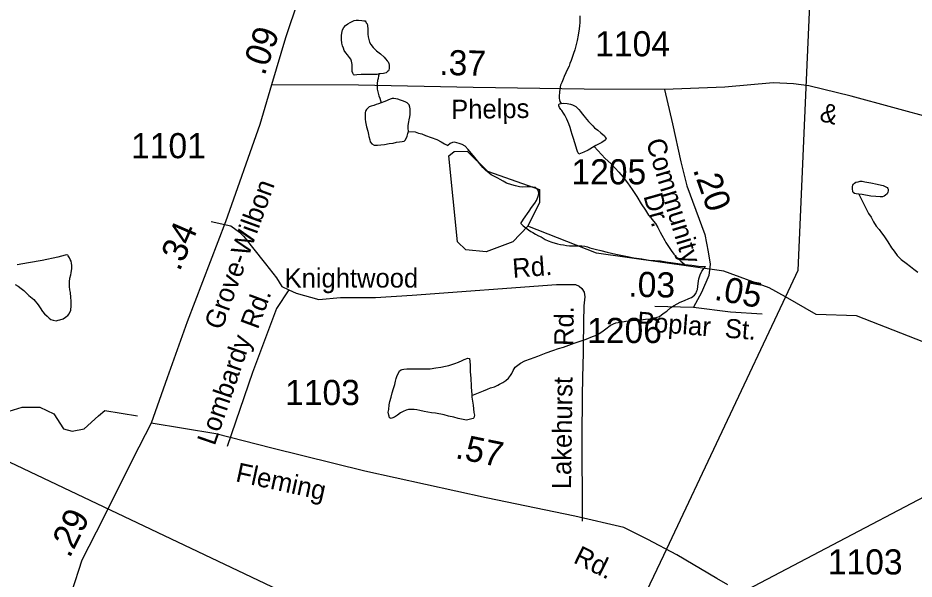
# Model space of a CAD drawing. Extents: x 2001466 to 2224147, y 644118 to 847247.
# Drawn here: x 2046028 to 2050483, y 665173 to 667963 of the extents above; entities that cross this region are included whole.
import ezdxf

# ---------------------------------------------------------------- set-up
doc = ezdxf.new("R2010")
doc.units = 0
for name, color, linetype in [('Exist Hydrographic Creek Single Shore', 7, 'Continuous'), ('Exist Hydrographic Misc Water Feature', 7, 'Continuous'), ('Exist Railroad Mainline', 7, 'Continuous'), ('Exist Road Non-System Type 51', 7, 'Continuous'), ('Exist Road Non-System Type 51 Label', 7, 'Continuous'), ('Exist Road Secondary Mileage Hundredths English Label', 7, 'Continuous'), ('Exist Road Secondary Type 41 Attributed', 7, 'Continuous'), ('Exist Road Secondary Type 51 Attributed', 7, 'Continuous'), ('Exist Road Secondary Type 51 Label', 7, 'Continuous'), ('Exist Road Secondary Type 51 Number Label', 7, 'Continuous'), ('Exist Utilities Electrical Transmission Line', 7, 'Continuous')]:
    doc.layers.add(name, color=color, linetype=linetype)

msp = doc.modelspace()

# ---------------------------------------------------------------- linework, layer by layer
at = {"layer": 'Exist Hydrographic Creek Single Shore'}
for points in [[(2049843.6, 666575.6), (2049763.4, 666621.1), (2049538.4, 666704.4), (2048905.4, 666792.7), (2048563.4, 666927.6)], [(2053273.2, 665427.7), (2053006.3, 665420.1), (2052782.4, 665359), (2052490.4, 665574.9), (2052414.3, 665701.1), (2052256.4, 665832.3), (2052022.2, 665948.5), (2051756.3, 665950.7), (2051539.3, 665974.8), (2051155.3, 666107.3), (2050197.3, 666481), (2049997.3, 666488.4), (2049843.6, 666575.6)]]:
    msp.add_lwpolyline(points, dxfattribs=at)
at = {"layer": 'Exist Hydrographic Misc Water Feature'}
for points in [[(2048822, 667974), (2048822, 667950), (2048822, 667940), (2048819.9, 667923.9), (2048818.1, 667907.9), (2048814, 667878), (2048808, 667850), (2048802.1, 667824), (2048796.1, 667804), (2048790.2, 667785.9), (2048786.3, 667775.9), (2048778.3, 667752), (2048772.4, 667736), (2048768.5, 667723.9), (2048760.5, 667707.9), (2048752.5, 667689.9), (2048744.5, 667671.9), (2048738.5, 667657.9), (2048732.6, 667641.9), (2048726.4, 667627.9), (2048722.5, 667609.9), (2048720.7, 667591.9), (2048718.6, 667575.8), (2048718.6, 667561.8), (2048720.7, 667555.9), (2048722.5, 667547.9), (2048728.7, 667537.9)], [(2047824.6, 667684.2), (2047812.7, 667682.1), (2047798.6, 667682.1), (2047782.6, 667682.1), (2047764.7, 667682.1), (2047734.6, 667682), (2047712.6, 667679.9), (2047700.5, 667677.9), (2047696.7, 667681.9), (2047692.5, 667687.9), (2047690.7, 667695.9), (2047690.5, 667705.9), (2047690.5, 667721.9), (2047690.5, 667732), (2047686.6, 667747.9), (2047682.5, 667757.9), (2047676.6, 667765.9), (2047666.3, 667779.9), (2047658.3, 667789.8), (2047650.3, 667801.8), (2047646.4, 667811.8), (2047642.3, 667823.8), (2047638.4, 667837.8), (2047636.4, 667855.8), (2047636.4, 667865.8), (2047636.4, 667875.8), (2047638.2, 667887.8), (2047642.3, 667903.8), (2047648.1, 667915.8), (2047656.1, 667925.8), (2047668.1, 667933.8), (2047680.2, 667939.9), (2047690.1, 667945.9), (2047700.1, 667949.9), (2047710.2, 667951.9), (2047722.1, 667951.9), (2047738.1, 667949.9), (2047748.1, 667948), (2047754.1, 667948), (2047758.2, 667944), (2047760.2, 667938), (2047764.1, 667934), (2047766.2, 667926), (2047766.2, 667920), (2047768.2, 667912), (2047768.2, 667906), (2047768.2, 667900), (2047768.2, 667890), (2047768.2, 667882), (2047770.3, 667868.1), (2047772.3, 667856.1), (2047776.2, 667842.1), (2047782.4, 667830.1), (2047794.5, 667816.1), (2047810.5, 667800.1), (2047830.3, 667784.2), (2047848.4, 667768.2), (2047856.4, 667760.2), (2047864.4, 667750.3), (2047868.5, 667744.3), (2047872.6, 667736.3), (2047874.4, 667728.3), (2047874.4, 667718.3), (2047874.4, 667712.3), (2047872.6, 667704.3), (2047870.5, 667700.2), (2047866.4, 667696.2), (2047858.4, 667690.2), (2047852.5, 667688.2), (2047846.5, 667686.2), (2047828.7, 667684.2), (2047824.6, 667684.2)], [(2047824.6, 667684.2), (2047820.7, 667674.2), (2047818.7, 667662.2), (2047816.6, 667652.2), (2047814.6, 667636.2), (2047814.6, 667626.2), (2047814.8, 667608.2), (2047818.7, 667588.2), (2047822.8, 667576.2), (2047826.9, 667564.2), (2047834.9, 667540.2)], [(2047834.9, 667540.2), (2047820.9, 667536.2), (2047808.8, 667532.2), (2047796.9, 667528.1), (2047784.8, 667524.1), (2047775, 667520.1), (2047766.8, 667512), (2047760.8, 667508), (2047756.9, 667500), (2047754.9, 667492.1), (2047755.1, 667482.1), (2047755.1, 667474.1), (2047755.1, 667460.1), (2047756.9, 667446.1), (2047761, 667422.1), (2047767.2, 667400.1), (2047771.1, 667384.1), (2047773.1, 667374.1), (2047777, 667356.2), (2047779.3, 667346.1), (2047787.3, 667336.2), (2047799.2, 667330.2), (2047815.2, 667330.2), (2047833.2, 667332.3), (2047851.3, 667334.3), (2047873.2, 667338.3), (2047893.3, 667340.4), (2047911.1, 667344.4), (2047925.1, 667346.5), (2047939, 667348.5), (2047949.1, 667350.5), (2047955.2, 667356.5), (2047963.2, 667374.5), (2047967.1, 667388.5), (2047969.2, 667398.5)], [(2047969.2, 667398.5), (2047969, 667414.5), (2047969, 667428.5), (2047971, 667446.5), (2047973.1, 667456.5), (2047977, 667470.5), (2047978.8, 667482.5), (2047978.8, 667496.5), (2047978.8, 667510.5), (2047977, 667518.5), (2047972.9, 667530.5), (2047962.8, 667540.4), (2047952.8, 667546.4), (2047940.7, 667550.4), (2047930.8, 667554.4), (2047916.7, 667558.4), (2047906.8, 667560.3), (2047896.8, 667562.3), (2047888.8, 667562.3), (2047878.7, 667558.3), (2047852.7, 667548.2), (2047834.9, 667540.2)], [(2048892.9, 667324.2), (2048863.2, 667306.2), (2048841, 667296.2), (2048825.1, 667288.1), (2048817.1, 667286.1), (2048815.2, 667290.1), (2048811.1, 667294.1), (2048807.2, 667308.1), (2048802.9, 667320.1), (2048797, 667342), (2048791, 667364), (2048783, 667384), (2048778.9, 667400), (2048773, 667418), (2048766.8, 667436), (2048762.9, 667448), (2048756.8, 667460), (2048746.7, 667480), (2048740.8, 667489.9), (2048732.8, 667501.9), (2048726.8, 667507.9), (2048720.7, 667517.9), (2048716.8, 667525.9), (2048716.6, 667531.8), (2048720.7, 667535.9), (2048728.7, 667537.9)], [(2048728.7, 667537.9), (2048738.7, 667539.9), (2048758.6, 667538), (2048774.6, 667534), (2048784.7, 667530), (2048794.7, 667526), (2048802.7, 667522), (2048808.6, 667516), (2048816.6, 667508.1), (2048824.8, 667498.1), (2048832.8, 667486.1), (2048842.7, 667474.1), (2048848.8, 667468.2), (2048856.8, 667458.2), (2048864.8, 667448.2), (2048886.8, 667426.2), (2048894.8, 667416.2), (2048911, 667404.3), (2048927, 667392.3), (2048944.8, 667376.4), (2048947.1, 667370.4), (2048953, 667362.4), (2048951, 667358.4), (2048947.1, 667354.4), (2048931.1, 667344.3), (2048900.9, 667328.3), (2048892.9, 667324.2)], [(2047969.2, 667398.5), (2048003.2, 667396.5), (2048019.2, 667390.6), (2048037, 667386.7), (2048055.1, 667378.7), (2048083.2, 667368.7), (2048111.1, 667358.8), (2048133.2, 667346.8), (2048149.2, 667336.8), (2048165.2, 667328.9)], [(2048527.7, 666941.6), (2048541.7, 666961.6), (2048569.8, 667001.7), (2048581.7, 667019.7), (2048597.6, 667041.7), (2048605.6, 667055.8), (2048613.4, 667071.8), (2048617.5, 667087.8), (2048615.5, 667103.8), (2048611.4, 667109.8), (2048599.5, 667119.7), (2048587.4, 667121.7), (2048575.5, 667123.7), (2048559.5, 667123.6), (2048537.6, 667121.6), (2048521.6, 667123.6), (2048501.5, 667127.5), (2048483.4, 667133.5), (2048457.4, 667141.5), (2048441.4, 667151.4), (2048425.4, 667159.4), (2048413.3, 667165.4), (2048381.3, 667183.3), (2048353.4, 667205.3), (2048339.3, 667219.2), (2048325.3, 667237.2), (2048313.2, 667253.2), (2048293.1, 667277.2), (2048281.3, 667291.1), (2048267.1, 667309.1), (2048251.1, 667325), (2048237.2, 667333), (2048221.2, 667338.9), (2048199, 667344.9), (2048189.2, 667342.9), (2048177.1, 667338.9), (2048165.2, 667328.9)], [(2048892.9, 667324.2), (2048947.1, 667264.3), (2048975.2, 667238.4), (2048997.3, 667216.5), (2049015.1, 667196.5), (2049037.3, 667170.5), (2049059.4, 667142.6), (2049081.4, 667110.6), (2049105.6, 667074.7), (2049127.5, 667038.7), (2049147.6, 667006.8), (2049163.6, 666982.8), (2049173.6, 666972.9), (2049179.6, 666962.9), (2049197.6, 666940.9), (2049209.7, 666920.9), (2049221.6, 666896.9), (2049229.8, 666883), (2049243.8, 666857), (2049249.9, 666847), (2049275.8, 666807), (2049289.9, 666789.1), (2049304.1, 666771.1), (2049323.9, 666753.1), (2049344, 666737.2)], [(2048563.4, 666927.6), (2048488.4, 666850.4), (2048355.3, 666800.7), (2048255.4, 666809.2), (2048213.4, 666849.5), (2048171.3, 667276.9), (2048196.4, 667299.3), (2048262.4, 667301.2), (2048362.5, 667200.8), (2048621.4, 667110.2), (2048621.4, 667044.6), (2048563.4, 666927.6)], [(2050209.2, 667086.8), (2050195.2, 667088.7), (2050187.2, 667090.7), (2050181.3, 667094.7), (2050179.2, 667098.7), (2050177.2, 667114.7), (2050177.2, 667124.7), (2050179, 667130.7), (2050183.1, 667136.7), (2050187, 667140.7), (2050193.2, 667146.7), (2050205.1, 667148.7), (2050215.1, 667150.7), (2050225.1, 667150.7), (2050239.1, 667148.8), (2050269, 667142.8), (2050299.2, 667136.9), (2050321.1, 667131), (2050329.1, 667129), (2050339.2, 667125), (2050343.1, 667123), (2050349, 667119), (2050353.1, 667115), (2050355.2, 667111), (2050355.2, 667103), (2050353.1, 667097), (2050349.2, 667089), (2050341.2, 667081), (2050335.3, 667077), (2050327.3, 667072.9), (2050315.2, 667072.9), (2050293.2, 667074.9), (2050269.2, 667076.9), (2050225.1, 667084.8), (2050209.2, 667086.8)], [(2050209.2, 667086.8), (2050247.3, 667010.8), (2050257.3, 666990.9), (2050269.4, 666972.9), (2050281.5, 666948.9), (2050295.5, 666926.9), (2050309.4, 666910.9), (2050321.5, 666895), (2050333.6, 666879), (2050353.5, 666849.1), (2050371.8, 666819.1), (2050383.7, 666803.1), (2050399.6, 666781.1), (2050419.7, 666761.2), (2050443.7, 666743.3), (2050465.9, 666727.3), (2050481.9, 666713.3), (2050501.8, 666699.4)], [(2048527.7, 666941.6), (2048539.8, 666929.6), (2048553.8, 666919.6), (2048565.9, 666909.7), (2048577.8, 666901.7), (2048587.8, 666895.8), (2048602, 666887.8), (2048615.9, 666879.8), (2048629.8, 666873.8), (2048649.9, 666861.8), (2048663.9, 666853.9), (2048681.9, 666847.9), (2048710, 666840), (2048726, 666836), (2048740, 666834), (2048756, 666832.1), (2048769.9, 666830.1), (2048785.9, 666830.1), (2048800, 666830.1), (2048819.9, 666830.2), (2048832, 666830.2), (2048846, 666828.2), (2048859.9, 666824.3), (2048872, 666820.3), (2048898.1, 666812.4), (2048925.9, 666806.4), (2048957.9, 666798.5), (2049000, 666788.5), (2049050, 666778.7), (2049090, 666770.7), (2049130, 666764.8), (2049166.1, 666758.8), (2049222, 666755), (2049249.9, 666751), (2049273.9, 666747), (2049344, 666737.2)], [(2046014.8, 666637), (2046029, 666629), (2046045, 666617), (2046056.8, 666607.1), (2046070.8, 666595.1), (2046082.9, 666583.1), (2046107.1, 666563.2), (2046129, 666537.2), (2046139.1, 666521.2), (2046151, 666503.3), (2046161, 666491.3), (2046173.1, 666479.3), (2046183.2, 666469.4), (2046191.2, 666463.4), (2046203.1, 666459.4), (2046219, 666457.4), (2046229.1, 666459.4), (2046237.1, 666461.4), (2046253.1, 666467.5), (2046265.2, 666475.5), (2046271.1, 666479.5), (2046277.1, 666483.5), (2046283, 666491.6), (2046291, 666509.5), (2046293.1, 666531.5), (2046292.9, 666555.5), (2046290.8, 666573.5), (2046289, 666597.5), (2046286.9, 666611.5), (2046284.7, 666627.5), (2046284.7, 666643.5), (2046284.7, 666651.5), (2046286.7, 666669.5), (2046290.6, 666685.5), (2046292.7, 666695.5), (2046296.6, 666717.5), (2046296.6, 666731.5), (2046294.7, 666743.5), (2046292.5, 666753.5), (2046288.6, 666761.5), (2046284.5, 666769.4), (2046278.5, 666779.4), (2046276.5, 666783.5), (2046270.5, 666785.4), (2046262.5, 666783.4), (2046226.4, 666773.3), (2046148.7, 666757.2), (2046080.6, 666745.1), (2046024.7, 666734.9)], [(2048285.4, 666085.3), (2048317.3, 666099.4), (2048343.4, 666109.4), (2048363.3, 666117.4), (2048377.4, 666123.5), (2048397.3, 666129.5), (2048413.3, 666137.6), (2048423.2, 666141.6), (2048439.1, 666149.6), (2048453.3, 666159.6), (2048467.2, 666171.7), (2048477.3, 666185.7), (2048483.2, 666195.7), (2048491, 666209.7), (2048501.1, 666225.7), (2048513.2, 666235.7), (2048527.1, 666245.8), (2048549.1, 666257.8), (2048576.9, 666267.8), (2048613, 666281.9), (2048655.1, 666298), (2048687.1, 666310), (2048714.9, 666320.1), (2048740.8, 666326.2), (2048792.9, 666346.2), (2048812.7, 666352.3), (2048832.8, 666358.3), (2048852.9, 666366.4), (2048884.7, 666378.4), (2048904.6, 666386.4), (2048930.7, 666402.5), (2048950.7, 666416.6), (2048972.7, 666434.5), (2048988.7, 666442.6), (2049000.6, 666446.6), (2049024.6, 666450.6), (2049050.6, 666454.7), (2049082.6, 666458.7), (2049112.5, 666460.8), (2049148.6, 666464.8), (2049174.7, 666466.9), (2049190.5, 666471), (2049206.4, 666475), (2049218.5, 666479), (2049236.4, 666493), (2049254.4, 666505), (2049274.5, 666523.1), (2049290.3, 666533.1), (2049306.3, 666541.2), (2049320.3, 666549.2), (2049342.4, 666557.2), (2049364.3, 666567.2), (2049376.4, 666573.3), (2049392.2, 666585.3), (2049398.2, 666593.3), (2049404.1, 666605.4), (2049406.2, 666613.4), (2049408.2, 666627.3), (2049410.3, 666643.3), (2049414.2, 666665.3), (2049420.1, 666685.4), (2049428.1, 666703.4), (2049440, 666719.4), (2049446, 666727.4)], [(2049344, 666737.2), (2049377.9, 666733.2), (2049411.9, 666729.3), (2049446, 666727.4)], [(2048285.4, 666085.3), (2048285.6, 666077.3), (2048291.5, 666037.3), (2048295.6, 666001.4), (2048297.7, 665987.4), (2048295.6, 665975.4), (2048291.5, 665971.3), (2048277.6, 665967.3), (2048257.7, 665963.3), (2048233.7, 665967.3), (2048217.5, 665971.2), (2048195.5, 665977.2), (2048169.5, 665983.1), (2048147.6, 665989.1), (2048103.7, 665997), (2048083.6, 665999), (2048047.5, 666006.9), (2048025.6, 666010.9), (2048011.6, 666014.8), (2047997.7, 666016.8), (2047983.5, 666016.8), (2047969.6, 666016.8), (2047957.7, 666012.7), (2047943.5, 666006.7), (2047929.6, 665998.7), (2047915.6, 665988.6), (2047899.7, 665978.6), (2047887.8, 665972.6), (2047883.7, 665970.6), (2047879.8, 665972.6), (2047875.7, 665974.6), (2047873.6, 665982.6), (2047871.8, 665988.6), (2047869.5, 666002.6), (2047871.6, 666016.5), (2047873.6, 666038.6), (2047877.5, 666056.6), (2047883.5, 666076.6), (2047889.4, 666098.6), (2047895.6, 666120.6), (2047901.3, 666140.6), (2047905.4, 666156.7), (2047909.3, 666170.6), (2047913.4, 666184.6), (2047921.2, 666200.6), (2047925.3, 666208.6), (2047933.3, 666212.6), (2047939.2, 666214.6), (2047947.2, 666216.7), (2047961.2, 666218.7), (2047979.2, 666218.8), (2047995.2, 666218.8), (2048009.2, 666218.8), (2048029.2, 666218.8), (2048047.3, 666218.9), (2048077.2, 666218.9), (2048105.1, 666222.9), (2048131.2, 666227), (2048153.3, 666231.1), (2048171.1, 666235.1), (2048201.1, 666245.1), (2048219.1, 666251.2), (2048237.2, 666259.2), (2048247, 666265.2), (2048265.1, 666271.3), (2048273.1, 666269.3), (2048277.2, 666237.3), (2048277.2, 666203.2), (2048279.2, 666171.3), (2048281.3, 666131.3), (2048283.3, 666103.3), (2048285.4, 666095.3), (2048285.4, 666085.3)]]:
    msp.add_lwpolyline(points, dxfattribs=at)
at = {"layer": 'Exist Railroad Mainline'}
msp.add_lwpolyline([(2046464.5, 663426.2), (2046524.6, 663459.1), (2048551.7, 664535.4), (2049194.6, 664876.7), (2049524.4, 665051.8), (2049557.2, 665070.3), (2052622.8, 666680.7), (2055671.2, 668278.9), (2056997.6, 668963.3), (2058840.6, 669936.5)], dxfattribs=at)
at = {"layer": 'Exist Road Non-System Type 51'}
for points in [[(2046989.7, 666951.2), (2047087, 666929.6), (2047130.2, 666897.2), (2047151.8, 666875.6), (2047195, 666821.6), (2047259.8, 666740.5), (2047313.8, 666670.3), (2047340.8, 666627.1), (2047375.2, 666611.2)], [(2047375.2, 666611.2), (2047411, 666594.6), (2047524.4, 666562.2), (2047632.4, 666573), (2047805.2, 666573), (2047988.8, 666583.8), (2048705.9, 666637.6), (2048769.9, 666638.3), (2048799.9, 666637.7), (2048817.7, 666629.3), (2048831.4, 666617.1), (2048843.1, 666598.8), (2048846.6, 666576.8), (2048841.7, 666530.9), (2048840.1, 666450.9), (2048837.1, 666206.9), (2048835, 666203), (2048831, 665907.1), (2048833.9, 665461)], [(2047375.2, 666611.2), (2047313.8, 666519), (2047195, 666200.3), (2047067.9, 665832)], [(2045729.8, 665879.7), (2045855.7, 665951.8), (2045942.1, 665995), (2046050.1, 666027.4), (2046136.5, 666027.4), (2046206.7, 665995), (2046255.3, 665919.3), (2046298.5, 665908.5), (2046357.9, 665919.3), (2046428.1, 665984.2), (2046460.5, 666011.2), (2046622.5, 665984.2)]]:
    msp.add_lwpolyline(points, dxfattribs=at)
at = {"layer": 'Exist Road Secondary Type 41 Attributed'}
msp.add_lwpolyline([(2049558.3, 665143.9), (2049503, 665175.3), (2049304.6, 665293.6), (2049160, 665369.6), (2049039.7, 665428.8), (2048796.9, 665485.8), (2048355.6, 665576.7), (2047752.9, 665709.7), (2047290.6, 665823.8), (2047011.9, 665895.7), (2046690.5, 665948.5)], dxfattribs=at)
at = {"layer": 'Exist Road Secondary Type 51 Attributed'}
for points in [[(2047420.9, 668051.6), (2047359.2, 667863.6), (2047289.5, 667630.1)], [(2047289.5, 667630.1), (2047230.4, 667433.7), (2047061, 666948.8), (2046869.9, 666452.3), (2046770.7, 666173.5), (2046690.5, 665948.5)], [(2049242.3, 667606.9), (2048843.3, 667607.9), (2048292.3, 667616.4), (2047721.8, 667629.1), (2047289.5, 667630.1)], [(2052557.1, 666646.2), (2052386.3, 666764), (2052162.5, 666885.4), (2051899.2, 667023.8), (2051726.1, 667110.4), (2051482.2, 667211.8), (2051238.9, 667288.9), (2050792.4, 667405.1), (2050170.2, 667573.1), (2049959.6, 667625.9), (2049883.6, 667635.4), (2049783.3, 667640.7), (2049542.6, 667618.5), (2049242.3, 667606.9)], [(2049242.3, 667606.9), (2049281.9, 667436.8), (2049323.1, 667247.7), (2049354.2, 667128.4), (2049442.9, 666885.4), (2049459.2, 666799.9), (2049469.8, 666738.6), (2049462.4, 666682.6), (2049426.5, 666598.1), (2049387.5, 666525.2)], [(2049194.8, 666530.5), (2049387.5, 666525.2)], [(2049387.5, 666525.2), (2049570.6, 666500.9), (2049728.9, 666491.4)], [(2046690.5, 665948.5), (2046600.2, 665771), (2046451.9, 665474.2), (2046346.4, 665266.1), (2046294.1, 665107.6), (2046236.1, 664901.7), (2046192.2, 664712.6), (2046166.9, 664540.4)]]:
    msp.add_lwpolyline(points, dxfattribs=at)
at = {"layer": 'Exist Utilities Electrical Transmission Line'}
msp.add_line((2049843.6, 666575.6), (2049237.5, 665290.3), dxfattribs=at)
for points in [[(2049847.4, 669402.6), (2049996.8, 668778.2), (2049945.8, 667617.3)], [(2049560.3, 664054.6), (2040710.9, 668262.4), (2038924.4, 668808.4)], [(2049945.8, 667617.3), (2049905.9, 666707.6), (2049843.6, 666575.6)], [(2049237.5, 665290.3), (2049120.8, 665042.8), (2049194.6, 664876.7)]]:
    msp.add_lwpolyline(points, dxfattribs=at)

# ---------------------------------------------------------------- texts
at = {"layer": 'Exist Road Non-System Type 51 Label'}
for s, rotation, p in [('Rd.', 4.2876, (2048489.6, 666670.7)), ('Rd.', 69.5587, (2047220.8, 666410.7)), ('Rd.', 89.3034, (2048789.4, 666331.5)), ('Lombardy', 70.9611, (2047006.3, 665832.6)), ('Lakehurst', 89.2213, (2048777.9, 665619.4))]:
    msp.add_text(s, height=95, rotation=rotation, dxfattribs=at).set_placement(p)
msp.add_text('Knightwood', height=95, dxfattribs=at).set_placement((2047354.1, 666622.3))
at = {"layer": 'Exist Road Secondary Mileage Hundredths English Label'}
for s, rotation, p in [('.09', 70.8534, (2047253.9, 667671.8)), ('.37', 358.9732, (2048122.2, 667679.2)), ('.20', 289.4804, (2049383, 667208.7)), ('.34', 66.5804, (2046831.6, 666699)), ('.03', 358.8252, (2049062, 666576.9)), ('.05', 349.3746, (2049485.7, 666562.7)), ('.57', 348.3661, (2048198.5, 665775.1)), ('.29', 63.6319, (2046285.2, 665273))]:
    msp.add_text(s, height=125, rotation=rotation, dxfattribs=at).set_placement(p)
at = {"layer": 'Exist Road Secondary Type 51 Label'}
for s, rotation, p in [('Phelps', 0.7901, (2048183, 667460.6)), ('&', 345.2788, (2050008.9, 667452.4)), ('Community', 286.8675, (2049149.9, 667348.1)), ('Grove-Wilbon', 70.0343, (2047041.5, 666406.9)), ('Dr.', 285.7356, (2049137.3, 667077.7)), ('Poplar  St.', 355.4686, (2049103.4, 666408.5)), ('Fleming', 347.6867, (2047106.3, 665660)), ('Rd.', 333.7274, (2048784.4, 665256.7))]:
    msp.add_text(s, height=95, rotation=rotation, dxfattribs=at).set_placement(p)
at = {"layer": 'Exist Road Secondary Type 51 Number Label'}
for s, p in [('1104', (2048898.1, 667772)), ('1101', (2046590.7, 667265.3)), ('1205', (2048780, 667135.3)), ('1206', (2048858, 666346.6)), ('1103', (2047356.4, 666038.1)), ('1103', (2050054.5, 665195.8))]:
    msp.add_text(s, height=125, dxfattribs=at).set_placement(p)

doc.saveas('drawing.dxf')
